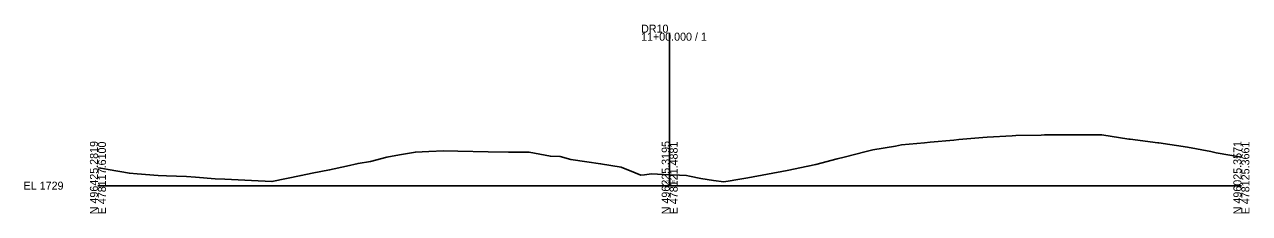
# Model space of a CAD drawing. Extents: x -26 to 403, y -10 to 2062.
# Drawn here: x -25.7 to 402.8, y 990.3 to 1056.3 of the extents above; entities that cross this region are included whole.
import ezdxf

# ---------------------------------------------------------------- set-up
doc = ezdxf.new("R2010")
doc.units = 0
for name, color, linetype in [('Exist Cross Section Cell', 7, 'Continuous'), ('Exist XS Center Line Elevation Label', 7, 'Continuous'), ('Exist XS Ground Line', 7, 'Continuous'), ('Scratch_Level_5', 7, 'Continuous')]:
    doc.layers.add(name, color=color, linetype=linetype)

msp = doc.modelspace()

# ---------------------------------------------------------------- linework, layer by layer
at = {"layer": 'Exist Cross Section Cell'}
for p, q in [((200, 1000), (200, 1053.42)), ((0, 1000), (200, 1000)), ((200, 1000), (400, 1000))]:
    msp.add_line(p, q, dxfattribs=at)
at = {"layer": 'Exist XS Ground Line'}
msp.add_lwpolyline([(0, 1006.27), (1, 1006.07), (3.52, 1005.64), (11, 1004.35), (13.72, 1004.16), (21.01, 1003.56), (23.93, 1003.43), (31.01, 1003.21), (34.13, 1003), (41.02, 1002.41), (44.33, 1002.32), (53.77, 1001.76), (60.87, 1001.44), (71.05, 1003.57), (74.93, 1004.37), (81.03, 1005.5), (86.9, 1006.78), (91.03, 1007.79), (95.34, 1008.39), (101.04, 1009.91), (105.54, 1010.77), (111.04, 1011.73), (115.74, 1011.99), (121.05, 1012.14), (125.94, 1012.06), (136.46, 1011.77), (143.59, 1011.71), (150.87, 1011.66), (158.31, 1010.28), (161.71, 1010.14), (165.4, 1009.1), (171.07, 1008.33), (175.83, 1007.69), (183.05, 1006.44), (187.95, 1004.47), (189.89, 1003.64), (191.14, 1003.82), (193.64, 1004.15), (200, 1003.82), (203.41, 1003.65), (205.93, 1003.54), (206.89, 1003.33), (210.92, 1002.56), (215.32, 1001.87), (218.99, 1001.3), (221.14, 1001.65), (223.16, 1002.05), (227.32, 1002.79), (241.09, 1005.27), (248.36, 1006.77), (251.1, 1007.42), (258.56, 1009.32), (261.1, 1009.99), (268.77, 1011.91), (271.1, 1012.47), (278.97, 1013.83), (281.11, 1014.24), (289.17, 1015.02), (291.11, 1015.22), (299.37, 1015.91), (301.12, 1016.14), (309.57, 1016.88), (311.12, 1016.97), (319.77, 1017.45), (321.12, 1017.54), (329.98, 1017.66), (331.13, 1017.72), (340.18, 1017.77), (341.13, 1017.79), (350.38, 1017.81), (351.13, 1017.8), (360.58, 1016.25), (361.14, 1016.19), (370.78, 1015.02), (371.14, 1014.98), (381.15, 1013.49), (389.28, 1011.89), (391.19, 1011.51), (400, 1009.94)], dxfattribs=at)
at = {"layer": 'Scratch_Level_5'}
msp.add_lwpolyline([(0, 1006.27), (1, 1006.07), (3.52, 1005.64), (11, 1004.35), (13.72, 1004.16), (21.01, 1003.56), (23.93, 1003.43), (31.01, 1003.21), (34.13, 1003), (41.02, 1002.41), (44.33, 1002.32), (53.77, 1001.76), (60.87, 1001.44), (71.05, 1003.57), (74.93, 1004.37), (81.03, 1005.5), (86.9, 1006.78), (91.03, 1007.79), (95.34, 1008.39), (101.04, 1009.91), (105.54, 1010.77), (111.04, 1011.73), (115.74, 1011.99), (121.05, 1012.14), (125.94, 1012.06), (136.46, 1011.77), (143.59, 1011.71), (150.87, 1011.66), (158.31, 1010.28), (161.71, 1010.14), (165.4, 1009.1), (171.07, 1008.33), (175.83, 1007.69), (183.05, 1006.44), (187.95, 1004.47), (189.89, 1003.64), (191.14, 1003.82), (193.64, 1004.15), (200, 1003.82), (203.41, 1003.65), (205.93, 1003.54), (206.89, 1003.33), (210.92, 1002.56), (215.32, 1001.87), (218.99, 1001.3), (221.14, 1001.65), (223.16, 1002.05), (227.32, 1002.79), (241.09, 1005.27), (248.36, 1006.77), (251.1, 1007.42), (258.56, 1009.32), (261.1, 1009.99), (268.77, 1011.91), (271.1, 1012.47), (278.97, 1013.83), (281.11, 1014.24), (289.17, 1015.02), (291.11, 1015.22), (299.37, 1015.91), (301.12, 1016.14), (309.57, 1016.88), (311.12, 1016.97), (319.77, 1017.45), (321.12, 1017.54), (329.98, 1017.66), (331.13, 1017.72), (340.18, 1017.77), (341.13, 1017.79), (350.38, 1017.81), (351.13, 1017.8), (360.58, 1016.25), (361.14, 1016.19), (370.78, 1015.02), (371.14, 1014.98), (381.15, 1013.49), (389.28, 1011.89), (391.19, 1011.51), (400, 1009.94)], dxfattribs=at)

# ---------------------------------------------------------------- texts
at = {"layer": 'Exist Cross Section Cell'}
for s, p in [('DR10', (190, 1053.42)), ('11+00.000 / 1', (190, 1050.62)), ('EL 1729', (-26, 998.6))]:
    msp.add_text(s, height=2.8, dxfattribs=at).set_placement(p)
for s, p in [('N 496425.2819', (0, 990)), ('E 478117.6100', (2.8, 990)), ('N 496225.3195', (200, 990)), ('E 478121.4881', (202.8, 990)), ('N 496025.3571', (400, 990)), ('E 478125.3661', (402.8, 990))]:
    msp.add_text(s, height=2.8, rotation=90, dxfattribs=at).set_placement(p)
at = {"layer": 'Exist XS Center Line Elevation Label'}
msp.add_text('1732.82', height=0.75, dxfattribs=at).set_placement((198.19, 1001.07))

doc.saveas('drawing.dxf')
